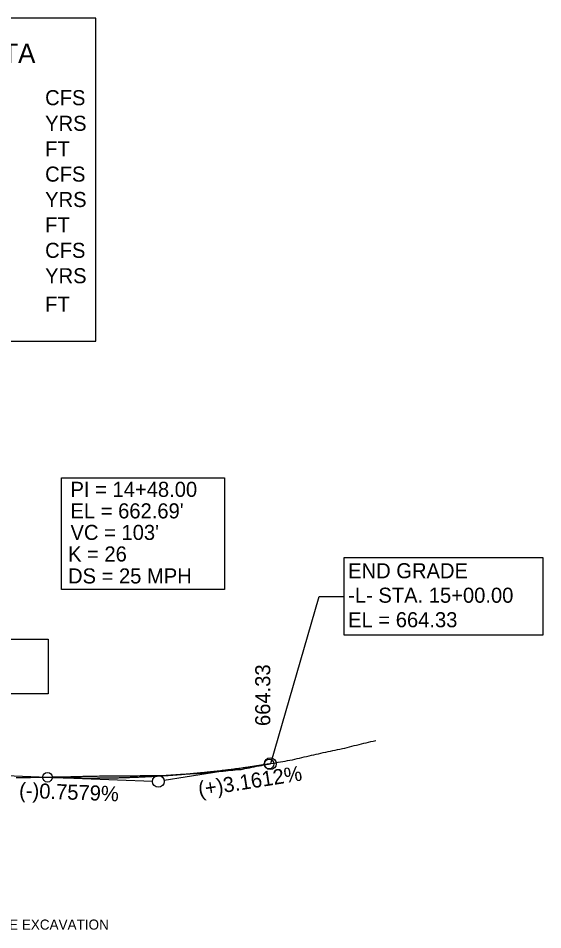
# Model space of a CAD drawing. Extents: x 566644 to 567306, y -52757 to -51996.
# Drawn here: x 567062.4 to 567306, y -52419.8 to -51996.4 of the extents above; entities that cross this region are included whole.
import ezdxf

# ---------------------------------------------------------------- set-up
doc = ezdxf.new("R2010")
doc.units = 0
for name, color, linetype in [('Prop Dimension Text', 7, 'Continuous'), ('Prop PFL Structure Hydraulic Data Label CELL', 7, 'Continuous'), ('Sheet Data Field CELL', 7, 'Continuous'), ('Sheet Plot Border Inside CELL', 7, 'Continuous'), ('Sheet Plot Border Outside CELL', 7, 'Continuous'), ('Sheet Profile Grid Major CELL', 7, 'Continuous'), ('Sheet Profile Grid Middle CELL', 7, 'Continuous'), ('Sheet Sticker Preliminary CELL', 7, 'Continuous')]:
    doc.layers.add(name, color=color, linetype=linetype)

msp = doc.modelspace()

# ---------------------------------------------------------------- linework, layer by layer
at = {"layer": 'Sheet Plot Border Inside CELL'}
for centre in [(567178.94, -52342.78), (567076.01, -52348.96)]:
    msp.add_circle(centre, 2.25, dxfattribs=at)
at = {"layer": 'Sheet Plot Border Outside CELL'}
for points in [[(566873.41, -52146.43), (567098.41, -52146.43), (567098.41, -51996.43), (566873.41, -51996.43)], [(567082.47, -52209.89), (567158.26, -52209.89), (567158.26, -52261.78), (567082.47, -52261.78)], [(567213.71, -52246.92), (567306.02, -52246.92), (567306.02, -52283.03), (567213.71, -52283.03)], [(566982.92, -52284.81), (567076.24, -52284.81), (567076.24, -52310.24), (566982.92, -52310.24)]]:
    msp.add_lwpolyline(points, close=True, dxfattribs=at)
at = {"layer": 'Sheet Profile Grid Major CELL'}
for p, q in [((567179.78, -52342.64), (567202.19, -52264.97)), ((567202.19, -52264.97), (567213.71, -52264.97)), ((567178.94, -52342.78), (567130.19, -52350.48)), ((567076.01, -52348.96), (567124.73, -52350.81))]:
    msp.add_line(p, q, dxfattribs=at)
for centre in [(567179.47, -52342.69), (567127.47, -52350.91)]:
    msp.add_circle(centre, 2.75, dxfattribs=at)
at = {"layer": 'Sheet Profile Grid Middle CELL'}
for p, q in [((566856.47, -52340.64), (567076.01, -52348.96)), ((567178.94, -52342.78), (567179.47, -52342.69))]:
    msp.add_line(p, q, dxfattribs=at)
msp.add_spline([(567076.01, -52348.96), (567078.07, -52349.03), (567080.12, -52349.1), (567082.18, -52349.16), (567084.24, -52349.21), (567086.3, -52349.25), (567088.36, -52349.28), (567090.42, -52349.31), (567092.48, -52349.33), (567094.54, -52349.34), (567096.59, -52349.34), (567098.65, -52349.33), (567100.71, -52349.32), (567102.77, -52349.29), (567104.83, -52349.26), (567106.89, -52349.22), (567108.95, -52349.18), (567111, -52349.12), (567113.06, -52349.06), (567115.12, -52348.99), (567117.18, -52348.91), (567119.24, -52348.82), (567121.3, -52348.72), (567123.36, -52348.62), (567125.42, -52348.51), (567127.47, -52348.39), (567129.53, -52348.26), (567131.59, -52348.13), (567133.65, -52347.98), (567135.71, -52347.83), (567137.77, -52347.67), (567139.83, -52347.5), (567141.88, -52347.33), (567143.94, -52347.14), (567146, -52346.95), (567148.06, -52346.75), (567150.12, -52346.54), (567152.18, -52346.32), (567154.24, -52346.1), (567156.3, -52345.87), (567158.35, -52345.63), (567160.41, -52345.38), (567162.47, -52345.12), (567164.53, -52344.86), (567166.59, -52344.58), (567168.65, -52344.3), (567170.71, -52344.01), (567172.77, -52343.72), (567174.82, -52343.41), (567176.88, -52343.1), (567178.94, -52342.78)], degree=3, dxfattribs=at)
at = {"layer": 'Sheet Sticker Preliminary CELL'}
for p, q in [((567072.53, -52348.95), (567073.64, -52348.93)), ((567073.64, -52348.93), (567074.75, -52348.91)), ((567074.75, -52348.91), (567075.85, -52348.89)), ((567075.85, -52348.89), (567076.96, -52348.87)), ((567076.96, -52348.87), (567078.06, -52348.85)), ((567078.06, -52348.85), (567079.17, -52348.83)), ((567079.17, -52348.83), (567080.27, -52348.81)), ((567080.27, -52348.81), (567081.38, -52348.79)), ((567081.38, -52348.79), (567082.48, -52348.78)), ((567082.48, -52348.78), (567083.59, -52348.76)), ((567083.59, -52348.76), (567084.7, -52348.74)), ((567084.7, -52348.74), (567085.8, -52348.72)), ((567085.8, -52348.72), (567086.91, -52348.7)), ((567086.91, -52348.7), (567088.01, -52348.68)), ((567088.01, -52348.68), (567088.6, -52348.67)), ((567088.6, -52348.67), (567089.12, -52348.65)), ((567089.12, -52348.65), (567090.22, -52348.61)), ((567090.22, -52348.61), (567091.33, -52348.58)), ((567091.33, -52348.58), (567092.44, -52348.54)), ((567092.44, -52348.54), (567093.54, -52348.5)), ((567093.54, -52348.5), (567094.1, -52348.48)), ((567094.1, -52348.48), (567094.65, -52348.47)), ((567094.65, -52348.47), (567095.75, -52348.46)), ((567095.75, -52348.46), (567096.86, -52348.44)), ((567096.86, -52348.44), (567097.96, -52348.43)), ((567097.96, -52348.43), (567099.07, -52348.41)), ((567099.07, -52348.41), (567100.17, -52348.4)), ((567100.17, -52348.4), (567101.28, -52348.39)), ((567101.28, -52348.39), (567102.39, -52348.38)), ((567102.39, -52348.38), (567103.49, -52348.36)), ((567103.49, -52348.36), (567104.6, -52348.35)), ((567104.6, -52348.35), (567105.7, -52348.34)), ((567105.7, -52348.34), (567106.81, -52348.33)), ((567106.81, -52348.33), (567107.91, -52348.32)), ((567107.91, -52348.32), (567109.03, -52348.31)), ((567109.03, -52348.31), (567110.12, -52348.3)), ((567110.12, -52348.3), (567111.23, -52348.29)), ((567111.23, -52348.29), (567112.34, -52348.28)), ((567112.34, -52348.28), (567113.44, -52348.28)), ((567113.44, -52348.28), (567114.55, -52348.27)), ((567114.55, -52348.27), (567115.65, -52348.26)), ((567115.65, -52348.26), (567116.76, -52348.25)), ((567116.76, -52348.25), (567117.86, -52348.25)), ((567117.86, -52348.25), (567118.97, -52348.24)), ((567118.97, -52348.24), (567120.07, -52348.23)), ((567120.07, -52348.23), (567121.18, -52348.23)), ((567121.18, -52348.23), (567122.29, -52348.22)), ((567122.29, -52348.22), (567123.39, -52348.22)), ((567123.39, -52348.22), (567124.5, -52348.22)), ((567124.5, -52348.22), (567125.6, -52348.21)), ((567125.6, -52348.21), (567126.71, -52348.21)), ((567126.71, -52348.21), (567127.81, -52348.21)), ((567127.81, -52348.21), (567128.92, -52348.17)), ((567061.48, -52349.07), (567062.58, -52349.07)), ((567062.58, -52349.07), (567063.69, -52349.07)), ((567063.69, -52349.07), (567064.8, -52349.06)), ((567064.8, -52349.06), (567066.46, -52349.06)), ((567066.46, -52349.06), (567067.01, -52349.05)), ((567067.01, -52349.05), (567068.11, -52349.03)), ((567068.11, -52349.03), (567069.22, -52349.01)), ((567069.22, -52349.01), (567070.32, -52348.99)), ((567070.32, -52348.99), (567071.61, -52348.97)), ((567071.61, -52348.97), (567072.53, -52348.95))]:
    msp.add_line(p, q, dxfattribs=at)
msp.add_lwpolyline([(567128.92, -52348.17), (567130.02, -52348.1), (567131.13, -52348.03), (567132.24, -52347.96), (567133.34, -52347.88), (567134.45, -52347.82), (567135.55, -52347.75), (567136.66, -52347.68), (567137.76, -52347.61), (567138.87, -52347.55), (567139.97, -52347.48), (567141.08, -52347.42), (567142.19, -52347.36), (567143.29, -52347.3), (567144.4, -52347.24), (567145.5, -52347.18), (567146.73, -52347.12), (567147.71, -52347.07), (567149.15, -52346.99), (567149.92, -52346.91), (567151.03, -52346.78), (567152.14, -52346.66), (567153.24, -52346.54), (567154.35, -52346.43), (567155.45, -52346.31), (567156.56, -52346.2), (567157.66, -52346.09), (567158.77, -52345.98), (567159.87, -52345.87), (567160.98, -52345.76), (567162.09, -52345.66), (567163.19, -52345.55), (567164.3, -52345.45), (567165.4, -52345.35), (567165.89, -52345.31), (567166.51, -52345.18), (567167.25, -52345.03), (567167.61, -52344.96), (567168.72, -52344.74), (567169.83, -52344.53), (567170.93, -52344.31), (567172.04, -52344.09), (567173.14, -52343.88), (567174.25, -52343.67), (567175.35, -52343.46), (567176.46, -52343.25), (567177.56, -52343.05), (567178.67, -52342.84), (567179.78, -52342.64), (567180.88, -52342.43), (567181.99, -52342.23), (567183.09, -52342.03), (567184.2, -52341.84), (567185.3, -52341.64), (567186.41, -52341.45), (567187.51, -52341.25), (567188.62, -52341.06), (567189.73, -52340.85), (567190.83, -52340.59), (567191.94, -52340.33), (567193.04, -52340.06), (567194.15, -52339.8), (567195.25, -52339.55), (567196.36, -52339.29), (567197.46, -52339.04), (567198.57, -52338.78), (567199.68, -52338.53), (567200.78, -52338.28), (567201.89, -52338.03), (567202.99, -52337.79), (567204.1, -52337.54), (567205.2, -52337.3), (567206.31, -52337.06), (567207.41, -52336.82), (567208.52, -52336.59), (567209.63, -52336.35), (567210.73, -52336.12), (567211.84, -52335.89), (567213.08, -52335.63), (567214.05, -52335.44), (567215.15, -52335.15), (567216.26, -52334.87), (567217.36, -52334.59), (567218.47, -52334.31), (567219.58, -52334.04), (567220.68, -52333.76), (567221.79, -52333.49), (567222.89, -52333.22), (567224, -52332.95), (567225.1, -52332.69), (567226.21, -52332.43), (567227.31, -52332.17), (567228.42, -52331.91)], dxfattribs=at)

# ---------------------------------------------------------------- texts
at = {"layer": 'Prop Dimension Text'}
msp.add_text('UNCLASSIFIED STRUCTURE EXCAVATION', height=4.6867, rotation=359.9999, dxfattribs=at).set_placement((566976.33, -52419.76))
at = {"layer": 'Prop PFL Structure Hydraulic Data Label CELL'}
for s, height, p in [('STRUCTURE HYDRAULIC DATA', 9, (566887.84, -52017.23)), ('CFS', 7, (567074.9, -52036.83)), ('YRS', 7, (567074.9, -52048.73)), ('FT', 7, (567074.9, -52060.53)), ('CFS', 7, (567074.9, -52072.33)), ('YRS', 7, (567074.9, -52084.13)), ('FT', 7, (567074.9, -52095.93)), ('CFS', 7, (567074.9, -52107.73)), ('YRS', 7, (567074.9, -52119.53)), ('FT', 7, (567074.9, -52132.72))]:
    msp.add_text(s, height=height, dxfattribs=at).set_placement(p)
at = {"layer": 'Sheet Data Field CELL'}
for s, rotation, p in [('(+)3.1612%', 8.9819, (567146.55, -52358.02)), ('(-)0.7579%', 357.8299, (567062.73, -52358.46))]:
    msp.add_text(s, height=7, rotation=rotation, dxfattribs=at).set_placement(p)
at = {"layer": 'Sheet Plot Border Inside CELL'}
for s, p in [("VC = 103'", (567086.69, -52238.75)), ('K = 26', (567085.53, -52248.77)), ('DS = 25 MPH', (567085.53, -52258.97))]:
    msp.add_text(s, height=7, dxfattribs=at).set_placement(p)
at = {"layer": 'Sheet Profile Grid Major CELL'}
for s, p in [('PI = 14+48.00', (567086.69, -52218.75)), ("EL = 662.69'", (567086.69, -52228.75)), ('END GRADE', (567215.63, -52256.56)), ('-L- STA. 15+00.00', (567215.63, -52267.93)), ('EL = 664.33', (567215.63, -52279.31))]:
    msp.add_text(s, height=7, dxfattribs=at).set_placement(p)
msp.add_text('664.33', height=7, rotation=90, dxfattribs=at).set_placement((567179.47, -52325.19))

doc.saveas('drawing.dxf')
